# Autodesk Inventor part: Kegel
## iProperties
Created: 2006-07
Part Number: Kegel
Document SubType Name: Blech
Designer: Robert Hüttner
Author: Robert Hüttner
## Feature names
1. Drehung1 [Revolution]
2. ExtrusionAbwicklung1
